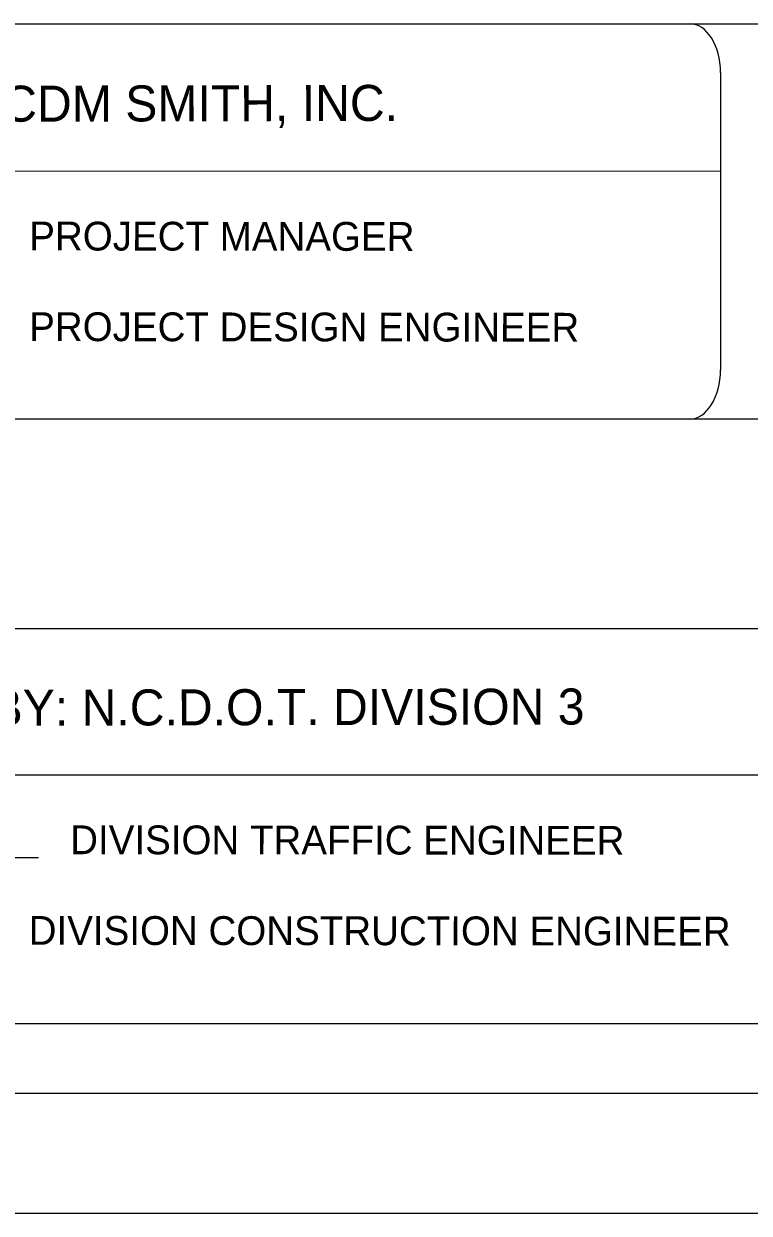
# Model space of a CAD drawing. Extents: x -2362 to 1945, y 0 to 1100.
# Drawn here: x 413.8 to 564.9, y 0 to 247.7 of the extents above; entities that cross this region are included whole.
import ezdxf

# ---------------------------------------------------------------- set-up
doc = ezdxf.new("R2010")
doc.units = 0
for name, color, linetype in [('Exist Utilities Telephone Test Hole SUE LOS A CELL', 7, 'Continuous'), ('Sheet_Plan_CELL', 7, 'Continuous'), ('Sheet_Title_Block_Text', 7, 'Continuous'), ('z - Construction', 7, 'Continuous')]:
    doc.layers.add(name, color=color, linetype=linetype)

msp = doc.modelspace()

# ---------------------------------------------------------------- linework, layer by layer
at = {"layer": 'Exist Utilities Telephone Test Hole SUE LOS A CELL'}
msp.add_line((0, 0), (1699.98, 0), dxfattribs=at)
at = {"layer": 'z - Construction'}
for p, q in [((267.24, 247.66), (765.08, 247.66)), ((558.95, 237.55), (558.93, 175.51)), ((260.8, 217.06), (558.94, 217)), ((765.05, 165.37), (267.21, 165.37)), ((267.21, 121.74), (710, 121.74)), ((260.78, 91.25), (716.4, 91.25)), ((269.54, 74.05), (416.87, 74.05)), ((709.97, 39.46), (267.18, 39.46)), ((38.07, 24.99), (1652, 24.99))]:
    msp.add_line(p, q, dxfattribs=at)
for centre, major_axis, start_param, end_param in [((552.53, 237.42), (0.01, 10.24), 4.725546, 6.283887), ((552.51, 175.61), (-0.01, -10.24), 0.000702, 1.571498)]:
    msp.add_ellipse(centre, major_axis=major_axis, ratio=0.62659, start_param=start_param, end_param=end_param, dxfattribs=at)

# ---------------------------------------------------------------- texts
at = {"layer": 'Sheet_Plan_CELL'}
for s, p in [('PROJECT MANAGER', (414.93, 200.47)), ('PROJECT DESIGN ENGINEER', (414.91, 181.6)), ('DIVISION TRAFFIC ENGINEER', (423.45, 74.76)), ('DIVISION CONSTRUCTION ENGINEER', (414.81, 55.89))]:
    msp.add_text(s, height=6, rotation=359.9372, dxfattribs=at).set_placement(p)
at = {"layer": 'Sheet_Title_Block_Text'}
for s, p in [('PLAN PREPARED BY: CDM SMITH, INC.', (303.4, 227.05)), ('PLAN REVIEWED BY: N.C.D.O.T. DIVISION 3', (321.62, 101.32))]:
    msp.add_text(s, height=7.5, rotation=0.1194, dxfattribs=at).set_placement(p)

doc.saveas('drawing.dxf')
